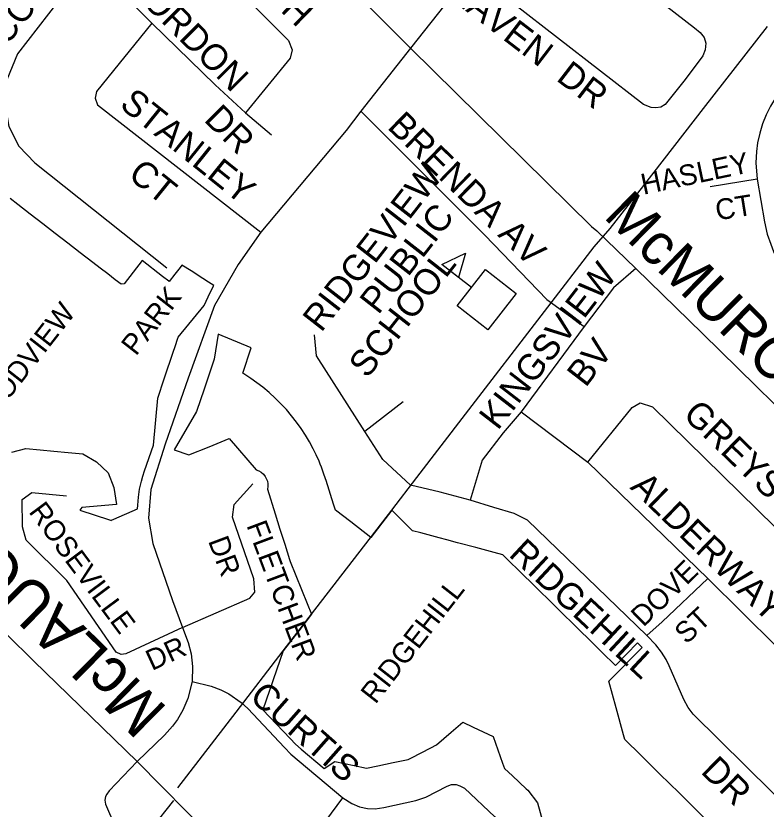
# Model space of a CAD drawing. Extents: x 586326 to 623965, y 4819854 to 4857850.
# Drawn here: x 599825 to 600548, y 4835757 to 4836521 of the extents above; entities that cross this region are included whole.
import ezdxf

# ---------------------------------------------------------------- set-up
doc = ezdxf.new("R2010")
doc.units = 0
for name, color, linetype in [('Lots_Concessions', 7, 'Continuous'), ('Major Rds and Hwys', 7, 'Continuous'), ('Major Rds Lbls', 7, 'Continuous'), ('Minor Rd Lbls', 7, 'Continuous'), ('Minor Rds', 7, 'Continuous'), ('Park Lbls', 7, 'Continuous'), ('Park Outlines', 7, 'Continuous'), ('Private Rds', 7, 'Continuous'), ('Proposed Secondary Rds', 7, 'Continuous'), ('School Syms_Lbls', 7, 'Continuous'), ('Secondary Rds Lbls', 7, 'Continuous')]:
    doc.layers.add(name, color=color, linetype=linetype)

msp = doc.modelspace()

# ---------------------------------------------------------------- linework, layer by layer
at = {"layer": 'Lots_Concessions'}
for p, q in [((600488.18, 4836431.54), (600549.76, 4836510.56)), ((600430.53, 4836357.57), (600488.18, 4836431.54)), ((600398.11, 4836315.98), (600430.53, 4836357.57)), ((600382.85, 4836298.57), (600398.11, 4836315.98)), ((600334.91, 4836236.25), (600382.85, 4836298.57)), ((600258.75, 4836137.22), (600334.91, 4836236.25)), ((600211.87, 4836076.23), (600258.75, 4836137.22)), ((600187.66, 4836044.73), (600211.87, 4836076.23)), ((600083.13, 4835909.17), (600187.66, 4836044.73)), ((600037.65, 4835850.17), (600083.13, 4835909.17)), ((599981.47, 4835777.27), (600037.65, 4835850.17)), ((599467.69, 4835121.14), (599977.65, 4835764.9))]:
    msp.add_line(p, q, dxfattribs=at)
at = {"layer": 'Major Rds and Hwys'}
for points in [[(599738.44, 4836002.09), (599842.66, 4835899.07), (599942.28, 4835802.44)], [(599942.28, 4835802.44), (600013.86, 4835729.92), (600054.2, 4835690.82)]]:
    msp.add_lwpolyline(points, dxfattribs=at)
at = {"layer": 'Minor Rds'}
for points in [[(599946.91, 4836638.86), (600088.2, 4836497.37), (600091.56, 4836488.15), (600089.88, 4836480.19), (600046.79, 4836427.51)], [(600318.74, 4836634), (600479.36, 4836509.56), (600484.98, 4836504.95), (600488.84, 4836500.01), (600490.45, 4836494.68), (600489.69, 4836488.21), (600487.51, 4836482.41), (600470.58, 4836459.63)], [(599896.78, 4836574.52), (599827.05, 4836484.51), (599816.74, 4836459.34), (599814.48, 4836438.73), (599818.6, 4836414.42), (599828.19, 4836395.28), (599843.66, 4836379.25), (599970.93, 4836278.03)], [(599896.78, 4836574.52), (599956.63, 4836513.92)], [(600659.58, 4836572.97), (600558.06, 4836442.82), (600552.61, 4836433.79), (600548.5, 4836425.65), (600544.88, 4836416.9), (600542.25, 4836407.92), (600540.25, 4836398.77), (600539.2, 4836390.16), (600538.67, 4836379.33), (600539.82, 4836363.54)], [(600470.58, 4836459.63), (600451.05, 4836435.46), (600447.01, 4836433.04), (600442.3, 4836432.22), (600437.55, 4836432.72), (600430.21, 4836435.67), (600264.5, 4836564.42)], [(599956.63, 4836513.92), (599903.14, 4836448.08), (599902, 4836441.56), (599904.26, 4836435.36), (600061.37, 4836312.67)], [(599956.63, 4836513.92), (600017.51, 4836454.6), (600046.79, 4836427.51)], [(600157.89, 4836429), (600277.46, 4836309.79), (600337.07, 4836247.58), (600372.98, 4836221.76)], [(600046.79, 4836427.51), (600071.9, 4836406.47)], [(600539.82, 4836363.54), (600494.56, 4836356.06)], [(600539.82, 4836363.54), (600546.89, 4836322.65), (600549.4, 4836310.5), (600552.88, 4836300.83), (600555.41, 4836293.92), (600559.21, 4836286.44), (600563.89, 4836278.72), (600569.95, 4836270.56), (600603.99, 4836236.39), (600711.07, 4836131.67), (600716.71, 4836127.15), (600721.92, 4836126.75), (600726.53, 4836129.97), (600788.72, 4836212.26)], [(600422.73, 4836277.5), (600401.41, 4836258.8), (600372.98, 4836221.76)], [(600372.98, 4836221.76), (600312.38, 4836139.47)], [(600161.8, 4836120.64), (600115.24, 4836193.33), (600113.37, 4836213.54)], [(600198.74, 4836148.92), (600161.8, 4836120.64)], [(600376.72, 4836090.84), (600419.37, 4836143.58), (600427.22, 4836148.07), (600438.82, 4836144.33), (600691.32, 4835896.69)], [(600312.38, 4836139.47), (600295.17, 4836119.27), (600274.96, 4836093), (600263.38, 4836054.18)], [(600312.38, 4836139.47), (600376.72, 4836090.84)], [(600263.38, 4836054.18), (600234.2, 4836062.03), (600205.77, 4836068.77), (600179.21, 4836093.46), (600161.8, 4836120.64)], [(600376.72, 4836090.84), (600492.24, 4835978.84)], [(599986.18, 4835931.48), (600050.9, 4835959.91), (600055.76, 4835965.52), (600054.64, 4835978.61), (600034.07, 4836038.09), (600035.94, 4836050.06), (600053.91, 4836069.96)], [(599986.18, 4835931.48), (599931.57, 4835906.42), (599926.87, 4835905.66), (599922.22, 4835907.91), (599874.71, 4835977.02), (599835.38, 4836015.92), (599831.98, 4836028.5), (599831.49, 4836054.89), (599840.74, 4836061.86), (599874.28, 4836058.5)], [(600433.41, 4835923.84), (600318.37, 4836035.1), (600305.65, 4836041.46), (600285.99, 4836047.37), (600263.38, 4836054.18)], [(600433.41, 4835923.84), (600448.13, 4835937.01), (600492.24, 4835978.84)], [(600492.24, 4835978.84), (600624.72, 4835847.84), (600629.75, 4835844.25), (600634.55, 4835842.45), (600638.99, 4835842.09), (600643.2, 4835843.06), (600646.95, 4835844.62), (600654.03, 4835850.6), (600671.24, 4835869.38), (600691.32, 4835896.69)], [(600629.88, 4835698.45), (600478.29, 4835848.08), (600473.37, 4835854.45), (600469.17, 4835862.33), (600454.98, 4835894.83), (600452.05, 4835900.8), (600447.54, 4835908), (600442.31, 4835914.86), (600433.41, 4835923.84)], [(599995.44, 4835879.47), (600013.61, 4835875.26), (600022.95, 4835871.71), (600030.57, 4835867.82), (600042.56, 4835859.43), (600048.84, 4835853.67), (600084.21, 4835815.98), (600090.58, 4835809.55), (600140.44, 4835767.44)], [(600140.44, 4835767.44), (600149.08, 4835761.91), (600156.6, 4835758.82), (600164.47, 4835757.27), (600171.71, 4835757.07), (600180.08, 4835758.16), (600210.73, 4835765.04), (600220.59, 4835768.31), (600240.93, 4835778.83), (600245.37, 4835780.33), (600249.67, 4835780.24), (600253.34, 4835779.2), (600257.63, 4835776.94), (600286.92, 4835749.35), (600290.45, 4835743.9), (600293.68, 4835737.01), (600317.53, 4835646.81), (600320.13, 4835641.23), (600323.91, 4835636.08), (600353.51, 4835606.13)], [(600188.57, 4835654.17), (600121.12, 4835720.55), (600117.8, 4835725.08), (600116.69, 4835729.24), (600116.8, 4835733.88), (600118.55, 4835737.83), (600140.44, 4835767.44)]]:
    msp.add_lwpolyline(points, dxfattribs=at)
at = {"layer": 'Park Outlines'}
for points in [[(599821.52, 4836100.67), (599835.11, 4836104.13), (599848.76, 4836102.86), (599862.05, 4836101.63), (599876.01, 4836100.34), (599890.09, 4836099.04), (599903.16, 4836091.2), (599914.3, 4836080.81), (599919.84, 4836066.62), (599922.55, 4836050.07), (599888.92, 4836047.24), (599888.13, 4836045.93), (599887.21, 4836044.71), (599915.62, 4836035.49), (599917.47, 4836034.89), (599917.64, 4836035.12), (599919.94, 4836036.11), (599942.83, 4836046), (599942.93, 4836049.36), (599943.56, 4836057.19), (599944.71, 4836064.95), (599946.39, 4836072.62), (599947.77, 4836077.58), (599949.37, 4836082.47), (599958.09, 4836107.26), (599962.23, 4836152.54), (599968.45, 4836171.11), (599977.45, 4836198), (599978.55, 4836201.3), (599981.88, 4836211.25), (600006.79, 4836242.04), (600010.67, 4836250.28), (600014.78, 4836258.41), (600016.21, 4836261.11), (600011.15, 4836264.37), (600005.57, 4836267.96), (599994.44, 4836275.14), (599985.5, 4836280.9), (599983.63, 4836278.48), (599978.78, 4836272.2), (599973.21, 4836264.98), (599972.97, 4836265.17), (599966.78, 4836269.97), (599947.13, 4836285.18), (599929.88, 4836262.91), (599926.84, 4836262.33), (599921.25, 4836266.65), (599914, 4836272.25), (599906.79, 4836277.83), (599899.53, 4836283.43), (599887.48, 4836292.75), (599875.43, 4836302.07), (599863.37, 4836311.39), (599851.32, 4836320.7), (599839.27, 4836330.02), (599827.21, 4836339.34), (599819.95, 4836344.95)], [(600497.2, 4835740.22), (600479.82, 4835757.32), (600464.62, 4835772.27), (600446.15, 4835790.44), (600427.69, 4835808.6), (600412.25, 4835823.79), (600411.04, 4835828.2), (600403.87, 4835854.35), (600396.87, 4835879.91), (600428.91, 4835912.5), (600424.57, 4835916.78), (600403.2, 4835895.05), (600390.17, 4835907.86), (600386.91, 4835911.07), (600377.13, 4835920.68), (600369.53, 4835928.16), (600364.09, 4835933.5), (600351.06, 4835946.32), (600338.02, 4835959.13), (600331.5, 4835965.54), (600324.98, 4835971.95), (600311.94, 4835984.77), (600298.91, 4835997.58), (600294.73, 4836001.69), (600286.49, 4836003.89), (600268.83, 4836008.61), (600251.16, 4836013.33), (600240.84, 4836016.08), (600233.5, 4836018.04), (600215.84, 4836022.76), (600207.81, 4836024.91), (600187.66, 4836044.73), (600167.43, 4836018.49), (600148.12, 4836033.37), (600133.32, 4836044.77), (600131.5, 4836050.59), (600124.39, 4836073.35), (600123.96, 4836074.72), (600122.07, 4836080.44), (600119.99, 4836086.09), (600118.85, 4836088.98), (600117.66, 4836091.83), (600114.96, 4836097.86), (600112.05, 4836103.79), (600108.42, 4836110.5), (600104.51, 4836117.05), (600100.34, 4836123.43), (600095.91, 4836129.63), (600091.18, 4836135.68), (600086.21, 4836141.53), (600080.93, 4836147.23), (600075.41, 4836152.71), (600069.53, 4836158.05), (600063.43, 4836163.14), (600057.78, 4836167.47), (600051.97, 4836171.57), (600046, 4836175.44), (600044.16, 4836176.57), (600052.36, 4836201.14), (600020.49, 4836214.3), (600016.62, 4836190.23), (600015.65, 4836187.33), (600006.94, 4836161.32), (599999.68, 4836139.63), (599977.89, 4836102.95), (599992.27, 4836097.9), (600011.58, 4836105.8), (600030.98, 4836113.73), (600056.92, 4836083.42), (600059.51, 4836082.51), (600061.89, 4836081.15), (600063.99, 4836079.39), (600065.75, 4836077.27), (600067.87, 4836072.72), (600068.35, 4836070.16), (600068.39, 4836067.56), (600067.98, 4836064.98), (600075.42, 4836041.16), (600079.99, 4836026.54), (600084.56, 4836011.92), (600089.13, 4835997.3), (600089.81, 4835995.14), (600095.2, 4835981.85), (600106.17, 4835954.84), (600110.36, 4835944.51), (600098.01, 4835928.48), (600083.13, 4835909.17), (600063.59, 4835852.45), (600089.66, 4835824.55), (600094.86, 4835819.32), (600100.36, 4835814.41), (600122.41, 4835795.9), (600132.95, 4835802.56), (600151.42, 4835798.62), (600163.34, 4835796.08), (600174.25, 4835798.34), (600189.17, 4835801.42), (600203.4, 4835804.36), (600206.79, 4835806.13), (600225.4, 4835815.84), (600230.85, 4835818.68), (600244.99, 4835830.82), (600256.02, 4835840.28), (600266.06, 4835835.64), (600285.35, 4835826.74), (600294.51, 4835800.81), (600296.29, 4835795.8), (600303.98, 4835788.62), (600317.34, 4835776.16), (600318.68, 4835774.91), (600328.04, 4835762.85), (600333.17, 4835744.22)]]:
    msp.add_lwpolyline(points, dxfattribs=at)
at = {"layer": 'Private Rds'}
msp.add_lwpolyline([(599942.28, 4835802.44), (599915.31, 4835774.14), (599913.15, 4835771.17), (599911.71, 4835768.69), (599911.28, 4835765.33), (599911.74, 4835761.57), (599970.66, 4835625.02)], dxfattribs=at)
at = {"layer": 'Proposed Secondary Rds'}
for points in [[(600098.03, 4836597.34), (600205.77, 4836489.98)], [(600264.5, 4836564.42), (600205.77, 4836489.98)], [(600205.77, 4836489.98), (600157.89, 4836429)], [(600205.77, 4836489.98), (600380.26, 4836317.92), (600385.34, 4836313.87), (600422.73, 4836277.5)], [(600157.89, 4836429), (600143.66, 4836410.6), (600061.37, 4836312.67)], [(600061.37, 4836312.67), (600039.53, 4836281.38), (600016.97, 4836241.76), (599991.42, 4836172.01), (599969.35, 4836108.42), (599955.37, 4836064.51), (599953.27, 4836036.97), (599957.47, 4836012.56), (599976.32, 4835957.66), (599986.18, 4835931.48)], [(600422.73, 4836277.5), (600487.02, 4836214.99), (600727.98, 4835978.61)], [(599986.18, 4835931.48), (599991.38, 4835917.22), (599994.41, 4835906.42), (599995.72, 4835894.08), (599995.44, 4835879.47)], [(599995.44, 4835879.47), (599991.33, 4835863.34), (599986.2, 4835851.96), (599981.1, 4835843.11), (599976.33, 4835836.54), (599968.67, 4835827.98), (599942.28, 4835802.44)]]:
    msp.add_lwpolyline(points, dxfattribs=at)
at = {"layer": 'School Syms_Lbls'}
msp.add_line((600264.42, 4836259.17), (600236.01, 4836281.36), dxfattribs=at)
for points in [[(600236.01, 4836281.36), (600258.79, 4836292.4), (600251.87, 4836268.89)], [(600250.78, 4836241.72), (600278.05, 4836276.62), (600307.66, 4836253.49), (600280.39, 4836218.59)]]:
    msp.add_lwpolyline(points, close=True, dxfattribs=at)

# ---------------------------------------------------------------- texts
at = {"layer": 'Major Rds Lbls'}
msp.add_text('McLAUGHLIN         RD S', height=43.4045, rotation=135.41681, dxfattribs=at).set_placement((599972.59, 4835853.3))
at = {"layer": 'Minor Rd Lbls'}
for s, height, rotation, p in [('LANGWITH', 25.002, 315.81847, (599970.53, 4836631.85)), ('CORBY CR', 24.996, 52.19498, (599816.65, 4836491.21)), ('TRELEAVEN  DR', 25.002, 322.50736, (600172.74, 4836591.68)), ('GORDON', 25.002, 315.00002, (599927.77, 4836552.47)), ('STANLEY', 25.002, 321.18863, (599924.31, 4836433.53)), ('DR', 25.002, 315.00002, (600005.82, 4836420.11)), ('BRENDA AV', 25.002, 315.76392, (600182.48, 4836413.1)), ('HASLEY', 19.998, 11.88868, (600430.11, 4836348.56)), ('CT', 25.002, 321.18863, (599932.43, 4836365.6)), ('CT', 19.998, 9.04221, (600501.2, 4836323.79)), ('KINGSVIEW', 25.002, 52.30578, (600289.84, 4836120.8)), ('BV', 25.002, 52.30578, (600374.48, 4836162.1)), ('GREYSTONE CR', 25.002, 315.90581, (600467.24, 4836135.3)), ('ALDERWAY AVE', 25.002, 315.83033, (600416.58, 4836066.04)), ('ROSEVILLE', 19.998, 306.62135, (599837.25, 4836043.07)), ('FLETCHER', 19.998, 290.55606, (600047.48, 4836030.1)), ('DR', 19.998, 290.55606, (600010.48, 4836015.1)), ('RIDGEHILL', 25.002, 316.97495, (600299.48, 4836001.1)), ('DOVE', 19.998, 44.21238, (600430.11, 4835931.27)), ('ST', 19.998, 42.83894, (600471.66, 4835914.78)), ('DR', 19.998, 24.65238, (599956.57, 4835889.66)), ('CURTIS', 24.996, 318.57635, (600049.48, 4835863.1)), ('DR', 25.002, 315.38198, (600484.48, 4835792.1))]:
    msp.add_text(s, height=height, rotation=rotation, dxfattribs=at).set_placement(p)
at = {"layer": 'Park Lbls'}
for s, p in [('PARK', (599941.2, 4836192.51)), ('WOODVIEW', (599788.68, 4836112.83)), ('RIDGEHILL', (600171.98, 4835857.02))]:
    msp.add_text(s, height=19.992, rotation=52.00002, dxfattribs=at).set_placement(p)
at = {"layer": 'School Syms_Lbls'}
for s, p in [('RIDGEVIEW', (600119.75, 4836215.19)), ('PUBLIC', (600174.71, 4836232.2)), ('SCHOOL', (600164.11, 4836170.74))]:
    msp.add_text(s, height=25, rotation=52.00002, dxfattribs=at).set_placement(p)
at = {"layer": 'Secondary Rds Lbls'}
msp.add_text('McMURCHY AV S', height=40.002, rotation=315.4825, dxfattribs=at).set_placement((600390.87, 4836326.94))

doc.saveas('drawing.dxf')
